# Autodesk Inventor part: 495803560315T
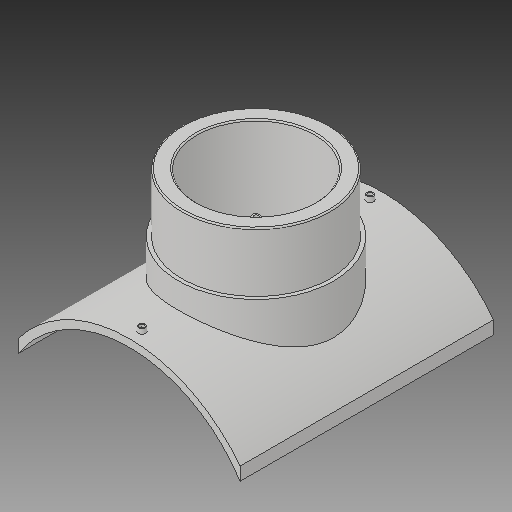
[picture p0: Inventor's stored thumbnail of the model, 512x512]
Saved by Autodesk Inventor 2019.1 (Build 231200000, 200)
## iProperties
Created: 2017-10
Part Number: 495803560315T
Material: Generic
Description: PLASSON BRANCH SADDLE 560x315
Document SubType Name: Modeling
Designer: KIM
Mass: 2754.05 g
Surface Area: 3037.44 cm^2
Volume: 2754.05 cm^3
Density: 1 g/cm^3
Appearance: Default
Author: KIM
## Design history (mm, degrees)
derived "495803.ipt"
feature "Solid1::495803.ipt"
tag "TaggingFeature1"
body "Solid1"
other parameters: "d1" = 16, "d2" = 472, "d4" = 0, "d12" = 305.6, "d13" = 14, "d14" = 243, "d16" = 5 deg, "d18" = 4, "d19" = 14, "d20" = 0, "d21" = 3, "d22" = 0, "d23" = 476, "d24" = 330.75, "d25" = 16, "d26" = 252, "d28" = 0, "d29" = 9.6, "d31" = 0, "d33" = 0, "d34" = 5.6, "d36" = 315, "d37" = 126, "d38" = 0, "d39" = 2.8, "d_1" = 315, "B_" = 472, "x_" = 16, "D_" = 16
